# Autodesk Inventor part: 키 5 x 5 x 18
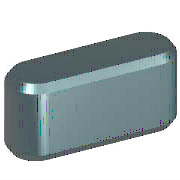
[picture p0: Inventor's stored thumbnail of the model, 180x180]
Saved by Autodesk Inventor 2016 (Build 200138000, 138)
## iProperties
IsCustomPart: 1
Created: 2012-02
Part Number: 키 5 x 5 x 18
Material: 강철, 연강
Description: 키 및 해당 키홈
Document SubType Name: Modeling
Standard: KS B 1311
Designer: mduedu
Standards Organization: KS
Language: ko-KR
Size Designation: 5 x 5 x 18
Categories: <MemberInstance><Categories><Category DisplayName="샤프트 부품" InternalName="7f7aeb1f-a693-4053-b835-cee3144e0d98" Mnemonic="SHFT"><Category DisplayName="키" Interna
Density: 7.86 g/cm^3
Appearance: 금색
Mass: 3.27476 g
Surface Area: 3.57848 cm^2
Volume: 0.416636 cm^3
Author: mduedu
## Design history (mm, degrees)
workplane "Work Plane1"
workplane "Work Plane2"
sketch "스케치1"
  geometry: L1 (2.5, 2.5)-(15.5, 2.5); L2 (15.5, -2.5)-(2.5, -2.5); L3 (0, 9.4)-(0, -7.4) reference; L4 (-5, 0)-(30, 0) reference; L5 (18, 0)-(18, 7); A1 r 2.5 centre (2.5, 0) between (2.5, 2.5) and (2.5, -2.5); A2 r 2.5 centre (15.5, 0) between (15.5, -2.5) and (15.5, 2.5)
  constraints: 6 end point, 5 point on circle, 4 tangent, 3 point on line, 2 centre point, 1 horizontal, 1 parallel, 1 perpendicular
  dimensions: "d0" = 2.5 radius of A1 (= 0.5 x PB); "d13" = 2.5 radius of A2 (= 0.5 x PB); "d14" = 18 distance between parallel lines of L5 L3 (= NLG)
extrude "본체1" new body sketch "스케치1" taper "d3" = 0 deg; stored distance "d4" = 10
workplane "Work Plane3"
body "Solid1"
chamfer "모따기1" distance "d8" = 0.4 (= PHH); stored, may be unused: second distance "d9" = 0.4 (= PHH), angle "d15" = 45 deg
other parameters: "d1" = -3 (= -PNT), "d2" = 2 (= PH - PNT), "NLG" = 18 [user parameter; used in 3 equation terms], "PB" = 5 [user parameter; used in 2 equation terms], "PNT" = 3 [user parameter; used in 2 equation terms], "PH" = 5 [user parameter; used in 1 equation term], "PHH" = 0.4 [user parameter; used in 2 equation terms], "d10" = 0, "d16" = 0, "d17" = 0, "d18" = 0, "WDMIN" = 12 [user parameter], "PLB2" = 18 (= NLG) [user parameter], "WDMAX" = 17 [user parameter], "PLB1" = 18 (= NLG) [user parameter], "RR" = 0.16 [user parameter], "PUEB" = 2.3 [user parameter]
